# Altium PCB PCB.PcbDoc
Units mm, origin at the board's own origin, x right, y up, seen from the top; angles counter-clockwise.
Board outline 152.4 x 101.6 mm, 2 copper layers (Top Layer, Bottom Layer); 11 components, 0 nets, 83 pads, 0 vias.
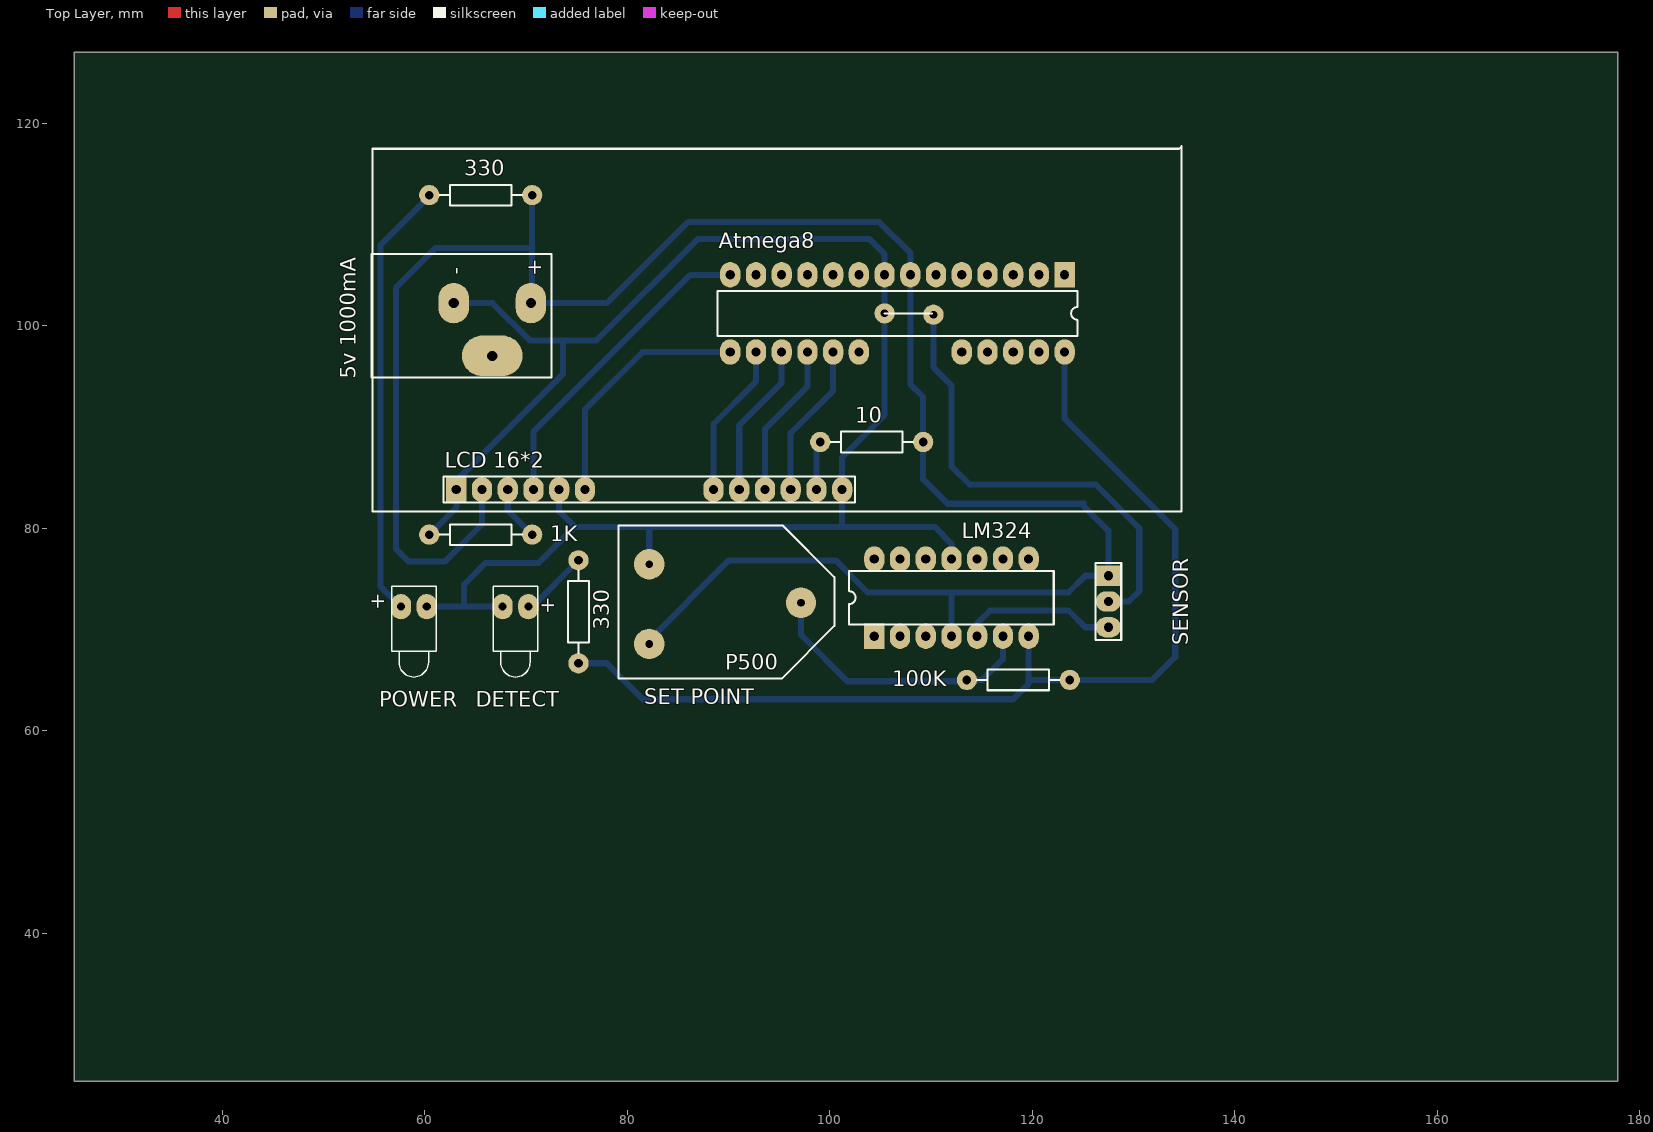
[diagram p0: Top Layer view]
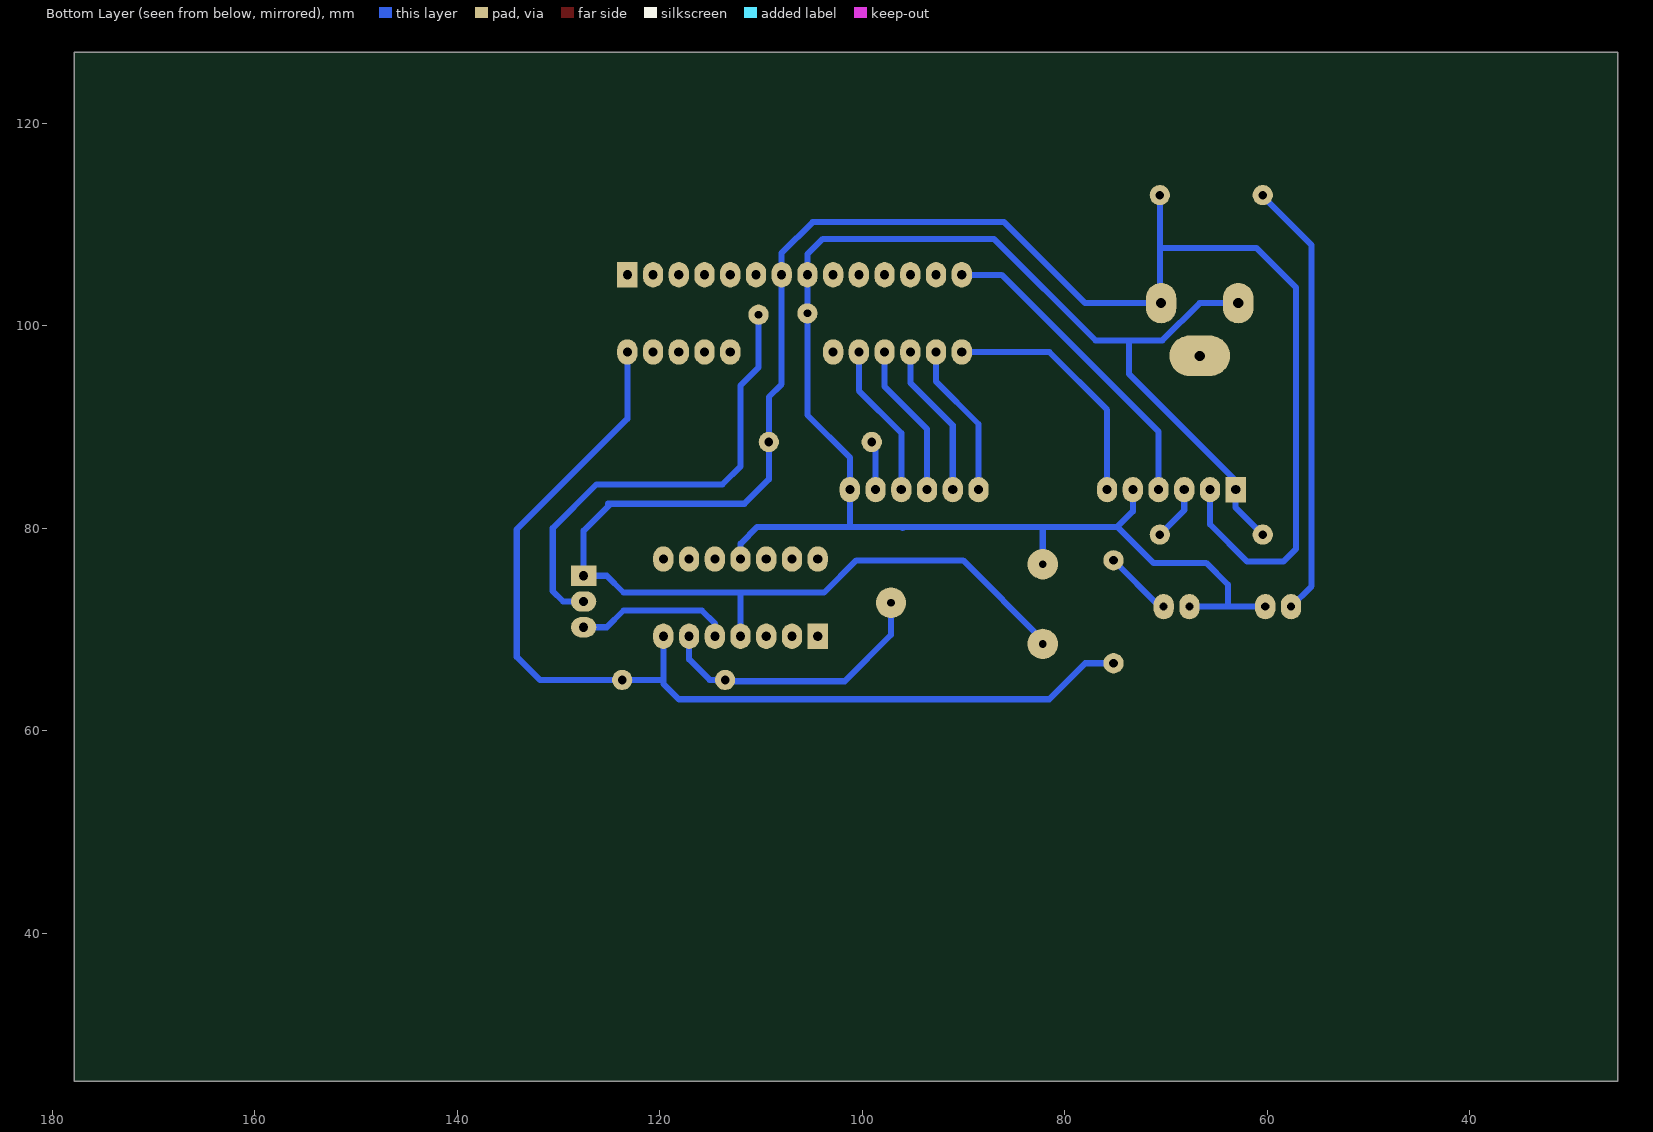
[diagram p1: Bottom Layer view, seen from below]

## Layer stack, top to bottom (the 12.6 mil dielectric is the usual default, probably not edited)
Top Layer: signal copper 0.0356
Dielectric: dielectric 0.32, FR-4, Dk 4.8
Bottom Layer: signal copper 0.0356

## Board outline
25.4,25.4 177.8,25.4 177.8,127 25.4,127

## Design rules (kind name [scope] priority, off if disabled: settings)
Clearance [All] p1: gap=0.254
ComponentClearance [All] p1: gap=0.254 collisioncheckmode=0
PolygonConnect [All] p1: connectstyle=Relief reliefconductorwidth=0.254 reliefentries=4 polygonreliefangle="90 Angle"
RoutingLayers [All] p1: top layer=Horizontal bottom layer=Vertical
RoutingVias [All] p1: holewidth=0.711 width=1.27 viastyle="Through Hole" minholewidth=0.711 minwidth=1.27 maxholewidth=0.711 maxwidth=1.27
SolderMaskExpansion [All] p1: expansion=0.102
TestPointUsage [All] p1: valid=0 allowmultiple=FALSE
Testpoint [All] p1: side=15 testpointundercomponent=TRUE minsize=1.016 maxsize=2.54 preferedsize=1.524 minholesize=0 maxholesize=1.016 preferedholesize=0.813 testpointgrid=0.025 style=1023 order=1234567890
Width [All] p1: maxlimit=0.254 minlimit=0.254 preferedwidth=0.254
16 further rules are at their usual default settings.

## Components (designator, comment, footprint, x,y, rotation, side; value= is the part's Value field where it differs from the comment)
1K "Comment" AXIAL-0.4 65.532,79.375 r0 top
10 "Comment" AXIAL-0.4 104.14,88.519 r0 top
100K "Comment" AXIAL-0.4 118.618,65.024 r0 top
330 "Comment" AXIAL-0.4 65.532,112.903 r0 top
330 "Comment" AXIAL-0.4 75.184,71.755 r90 top
Atmega8 "Comment" 28P3 106.68,101.219 r180 top
DETECT "Comment" LED-1 68.961,72.263 r270 top
"LCD 16*2" "Comment" HDR1X16 63.119,83.82 r0 top
LM324 "Comment" DIP-14 112.014,73.152 r0 top
POWER "Comment" LED-1 58.928,72.263 r270 top
SENSOR "Comment" HDR1X3 127.508,75.311 r270 top

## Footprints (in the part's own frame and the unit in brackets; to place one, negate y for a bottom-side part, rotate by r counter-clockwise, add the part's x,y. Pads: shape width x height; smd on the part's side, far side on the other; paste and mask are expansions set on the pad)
28P3 [mm] "DIP; 28 Leads; Row Spacing 7.62 mm; Pitch 2.54 mm"
  rect 2x2.5 hole 0.9: 1(-16.51,-3.81)
  oval 2x2.5 hole 0.9: 2(-13.97,-3.81) 3(-11.43,-3.81) 4(-8.89,-3.81) 5(-6.35,-3.81) 6(-3.81,-3.81) 7(-1.27,-3.81) 8(1.27,-3.81) 9(3.81,-3.81) 10(6.35,-3.81) 11(8.89,-3.81) 12(11.43,-3.81) 13(13.97,-3.81) 14(16.51,-3.81) 15(16.51,3.81) 16(13.97,3.81) 17(11.43,3.81) 18(8.89,3.81) 19(6.35,3.81) 20(3.81,3.81) 24(-6.35,3.81) 25(-8.89,3.81) 26(-11.43,3.81) 27(-13.97,3.81) 28(-16.51,3.81)
  round 0 all layers, no hole: 21(1.27,3.81) 22(-1.27,3.81) 23(-3.81,3.81)
  silkscreen extent -17.78,-2.23 17.78,2.23
AXIAL-0.4 [mm]
  round 2 hole 0.85: 1(-5.08,0) 2(5.08,0)
  silkscreen extent -4.06,-1.02 4.06,1.02
DIP-14 [mm]
  rect 2x2.5 hole 0.9: 1(-7.62,-3.81)
  oval 2x2.5 hole 0.9: 2(-5.08,-3.81) 3(-2.54,-3.81) 4(0,-3.81) 5(2.54,-3.81) 6(5.08,-3.81) 7(7.62,-3.81) 8(7.62,3.81) 9(5.08,3.81) 10(2.54,3.81) 11(0,3.81) 12(-2.54,3.81) 13(-5.08,3.81) 14(-7.62,3.81)
  silkscreen extent -10.1,-2.65 10.1,2.65
HDR1X3 [mm] "Connector; Header; 3 Position"
  rect 2x2.5 hole 0.9: 1(0,0)
  oval 2x2.5 hole 0.9: 2(2.54,0) 3(5.08,0)
  silkscreen extent -1.27,-1.27 6.35,1.27
HDR1X16 [mm] "Connector; Header; 16 Position"
  rect 2x2.5 hole 0.9: 1(0,0)
  oval 2x2.5 hole 0.9: 2(2.54,0) 3(5.08,0) 4(7.62,0) 5(10.16,0) 6(12.7,0) 11(25.4,0) 12(27.94,0) 13(30.48,0) 14(33.02,0) 15(35.56,0) 16(38.1,0)
  round 0 all layers, no hole: 7(15.24,0) 8(17.78,0) 9(20.32,0) 10(22.86,0)
  silkscreen extent -1.27,-1.27 39.37,1.27
LED-1 [mm]
  oval 2.5x2 hole 0.8: 1(0,1.27) 2(0,-1.27)
  silkscreen extent -2,-2.2 6.95,2.2

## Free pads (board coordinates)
  oval 3x4 hole 1: 0(70.485,102.235) 1(62.865,102.235)
  round 3 hole 0.762: 0(82.169,68.58) 0(82.169,76.454) 0(97.155,72.644)
  round 2 hole 0.762: 1(110.236,101.092) 2(105.41,101.219)
  oval 6x4 hole 1: 2(66.675,97.028)

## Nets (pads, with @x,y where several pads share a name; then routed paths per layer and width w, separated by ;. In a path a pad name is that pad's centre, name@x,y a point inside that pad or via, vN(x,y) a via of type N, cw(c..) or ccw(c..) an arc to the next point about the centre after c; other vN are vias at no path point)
pads on no net: 1K.1 1K.2 10.1 10.2 100K.1 100K.2 330.1 330.2 "LCD 16*2.1" "LCD 16*2.2" "LCD 16*2.3" "LCD 16*2.4" "LCD 16*2.5" "LCD 16*2.6" "LCD 16*2.7" "LCD 16*2.8" "LCD 16*2.9" "LCD 16*2.10" "LCD 16*2.11" "LCD 16*2.12" "LCD 16*2.13" "LCD 16*2.14" "LCD 16*2.15" "LCD 16*2.16" Atmega8.1 Atmega8.2 Atmega8.3 Atmega8.4 Atmega8.5 Atmega8.6 Atmega8.7 Atmega8.8 Atmega8.9 Atmega8.10 Atmega8.11 Atmega8.12 Atmega8.13 Atmega8.14 Atmega8.15 Atmega8.16 Atmega8.17 Atmega8.18 Atmega8.19 Atmega8.20 Atmega8.21 Atmega8.22 Atmega8.23 Atmega8.24 Atmega8.25 Atmega8.26 Atmega8.27 Atmega8.28 DETECT.1 DETECT.2 LM324.1 LM324.2 LM324.3 LM324.4 LM324.5 LM324.6 LM324.7 LM324.8 LM324.9 LM324.10 LM324.11 LM324.12 LM324.13 LM324.14 POWER.1 POWER.2 SENSOR.1 SENSOR.2 SENSOR.3
copper on no net: | length 760.7
  Top Layer w1: 62.865,101.981 62.865,102.235 ; 69.596,101.346 69.596,102.87 70.358,103.632 ; 70.485,102.235 71.247,101.473
  Bottom Layer w0.6: 57.658,72.263 55.626,74.295 55.626,75.565 55.626,107.95 60.452,112.776 60.452,112.903 ; 59.817,72.263 67.691,72.263 ; 60.198,72.263 60.325,72.136 ; 60.452,79.375 63.119,82.042 63.119,83.82 ; 62.865,83.82 63.119,83.82 ; 62.865,102.235 66.675,102.235 70.358,98.552 76.962,98.552 86.995,108.585 103.886,108.585 105.41,107.061 105.41,105.029 105.41,91.186 101.219,86.995 101.219,83.82 101.219,80.264 ; 63.881,72.263 63.881,74.422 66.04,76.581 71.247,76.581 74.803,80.137 ; 65.659,83.82 65.659,80.391 61.976,76.708 58.42,76.708 57.15,77.978 57.15,103.759 61.087,107.696 70.612,107.696 ; 68.199,83.82 68.199,81.788 70.612,79.375 ; 70.231,72.263 70.612,72.263 75.184,76.835 ; 70.485,102.235 77.978,102.235 85.979,110.236 104.902,110.236 107.95,107.188 107.95,105.029 107.95,94.234 109.22,92.964 109.22,88.519 109.22,84.836 111.633,82.423 125.095,82.423 ; 70.612,102.235 70.612,112.903 ; 70.739,83.82 70.739,89.535 86.233,105.029 90.17,105.029 ; 73.279,83.82 73.279,81.661 74.803,80.137 ; 73.66,98.552 73.66,95.25 63.119,84.709 63.119,83.82 ; 75.184,66.675 77.978,66.675 81.534,63.119 118.11,63.119 119.634,64.643 119.634,69.342 119.634,67.056 ; 75.819,83.82 75.819,91.694 81.534,97.409 90.17,97.409 ; 82.169,68.58 82.169,68.961 90.043,76.835 100.584,76.835 103.759,73.66 121.031,73.66 ; 82.169,76.454 82.169,80.137 ; 88.519,83.82 88.519,90.297 92.71,94.488 92.71,97.409 ; 91.059,83.82 91.059,90.17 95.25,94.361 95.25,97.409 ; 93.599,83.82 93.599,89.789 97.79,93.98 97.79,97.409 ; 95.885,80.137 96.012,80.01 ; 96.139,83.82 96.139,89.408 100.33,93.599 100.33,97.409 ; 97.155,72.898 97.155,69.469 101.727,64.897 113.411,64.897 113.538,65.024 115.062,65.024 117.094,67.056 117.094,69.342 ; 98.679,83.82 98.679,88.392 ; 98.806,80.137 110.363,80.137 112.014,78.486 112.014,76.962 ; 99.314,80.137 74.803,80.137 ; 110.236,101.092 110.236,95.885 112.014,94.107 112.014,86.106 113.792,84.328 126.238,84.328 130.556,80.01 130.556,73.787 129.54,72.771 127.508,72.771 ; 112.014,69.342 112.014,73.66 ; 114.554,69.342 114.554,70.612 115.824,71.882 121.793,71.882 123.571,71.882 125.222,70.231 127.508,70.231 ; 119.634,65.024 123.698,65.024 126.619,65.024 131.826,65.024 131.953,65.151 134.112,67.31 134.112,79.883 123.19,90.805 123.19,91.186 123.19,97.409 ; 120.777,73.66 123.571,73.66 125.222,75.311 127.508,75.311 127.508,79.756 124.841,82.423

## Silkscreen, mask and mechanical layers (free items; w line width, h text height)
Top Overlay:
  lines w0.2: 105.41,101.219 110.109,101.219 ; 54.737,94.869 54.737,107.061 69.977,107.061 72.517,107.061 72.517,94.869 54.737,94.869 ; 54.864,81.661 134.747,81.661 134.747,117.729 134.493,117.475 54.864,117.475 54.864,81.661 ; 79.121,65.151 95.25,65.151 100.457,70.358 100.457,75.184 95.377,80.264 79.121,80.264 79.121,79.629 79.121,65.151
  text "-" at 63.754,105.029 h1.52 r90
  text "+" at 71.501,104.902 h1.52 r90
  text "5v 1000mA" at 53.213,94.742 h1.52 r90
  text "+" at 56.007,71.882 h1.52 r90
  text "+" at 72.771,71.501 h1.52 r90
  text "P500" at 89.662,66.04 h1.52
  text "SET POINT" at 81.661,62.611 h1.52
